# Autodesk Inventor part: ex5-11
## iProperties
Author: Administrator
Created: 2001-09
Part Number: ex5-11
Document SubType Name: Modeling
Designer: Administrator
Control State: 0
Master: False
Checked Out: False
PropertySet Name: Design Tracking Control
Length Units: 11272
Angle Units: 11279
Time Units: 11290
Mass Units: 11286
Shininess: 3
Angle Display Precision: 2
Document Length Units: 11272
Document Angle Units: 11286
Document Time Units: 11279
Document Mass Units: 11290
Document Length Units Precision: 3
Document Angle Units Precision: 2
Compacted: False
PropertySet Name: _Private Model Information
Density: 0.0
Volumn: 0.0
Area: 0.0
PropertySet Name: Model Information
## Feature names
1. Revolution1
2. Hole1
3. Shell1
4. Loft1
5. Sweep1
6. Coil1
7. Fillet1
8. Chamfer1
9. keyhole [Extrusion]
